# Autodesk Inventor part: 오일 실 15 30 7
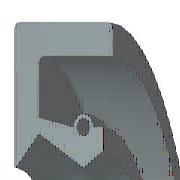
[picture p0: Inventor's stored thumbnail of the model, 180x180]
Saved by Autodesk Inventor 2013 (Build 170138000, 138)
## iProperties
IsCustomPart: 1
Created: 2012-02
Part Number: 오일 실 15 30 7
Material: 고무
Description: 오일-실
Document SubType Name: Modeling
Standard: KS B 2804
Designer: mduedu
Standards Organization: KS
Language: ko-KR
Size Designation: D - 15 30 7
Categories: <MemberInstance><Categories><Category DisplayName="샤프트 부품" InternalName="7f7aeb1f-a693-4053-b835-cee3144e0d98" Mnemonic="SHFT"><Category DisplayName="실링" Intern
Density: 0.93 g/cm^3
Author: mduedu
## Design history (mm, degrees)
revolve "본체" stored, may be unused: angle "d17" = 90 deg
revolve "스프링1" stored, may be unused: angle "d18" = 90 deg
body "Solid1"
sketch "스케치1"
  geometry: L1 (0, 15)-(7, 15); L2 (7, 13.25)-(1.75, 13.25); L3 (1.75, 9.25)-(4.9, 7.5); L4 (4.9, 7.5)-(0, 7.5); L5 (0, 0)-(9.586, 0) reference; L6 (4.9, 7.5)-(6.3, 8.375); L7 (0, 18)-(0, -3) reference; L8 (-1.941, 0)-(11.507, 0) reference; L9 (4.2, 9.6)-(1.75, 10.09); L10 (1.75, 10.09)-(1.75, 13.25); L11 (0, 15)-(0, 7.588); L12 (4.9, 7.5)-(0, 7.5); L13 (1.75, 9.25)-(0.152, 7.528); L14 (7, 15)-(7, 13.25); L15 (5.6, 9.6)-(6.3, 9.6); L16 (6.3, 9.6)-(6.3, 8.375); C1 r 0.455 at (4.9, 9.6); A1 r 0.7 centre (4.9, 9.6) between (5.6, 9.6) and (4.2, 9.6); A2 r 0.088 centre (0.088, 7.588) between (0, 7.588) and (0.152, 7.528); 1 further point
  constraints: 28 end point, 5 horizontal alignment, 5 point on line, 4 point on circle, 4 vertical alignment, 3 centre point, 3 tangent, 2 collinear, 2 horizontal, 2 perpendicular, 1 coincident, 1 parallel
  dimensions: "d0" = 30 diameter of L1 L5 (= SD2); "d1" = 1.75 distance of L1.end L2.start (= SD); "d2" = 0.91 diameter of C1 (= SPDI); "d3" = 1.4 diameter of A1 (= SPDA); "d4" = 15 diameter of L3.end L5 (= NND); "d5" = 18.5 diameter of L3.start L5 (= TKDM); "d7" = 20.18 diameter of L9.end L5 (= TKDM + 0.24 x SWDT); "d8" = 1.75 distance between parallel lines of L11 L10 (= SD); "d9" = 4.9 distance from line of L11 C1.centre (= SPDST); "d10" = 19.2 diameter of C1.centre L5 (= HLDM); "d11" = 0.0875 radius of A2 (= 0.25 x LAB); "d12" = 6.3 distance between parallel lines of L11 L16 (= SDI); "d13" = 16.75 diameter of L6.end L5 (= ABDM); "d14" = 7 distance from line of L11 L1.end (= SWDT)
fillet "모깎기1" dims "d6" = 0.3 (= RR)
other parameters: "SD2" = 30 [user parameter; used in 1 equation term], "SWDT" = 7 [user parameter; used in 2 equation terms], "RR" = 0.3 [user parameter; used in 1 equation term], "SD" = 1.75 [user parameter; used in 2 equation terms], "NND" = 15 [user parameter; used in 1 equation term], "SPDA" = 1.4 [user parameter; used in 1 equation term], "SPDI" = 0.91 [user parameter; used in 1 equation term], "TKDM" = 18.5 [user parameter; used in 2 equation terms], "HLDM" = 19.2 [user parameter; used in 1 equation term], "ABDM" = 16.75 [user parameter; used in 1 equation term], "SDI" = 6.3 [user parameter; used in 1 equation term], "SPDST" = 4.9 [user parameter; used in 1 equation term], "LAB" = 0.35 [user parameter; used in 1 equation term], "d15" = 0, "d16" = 0, "d19" = 0
